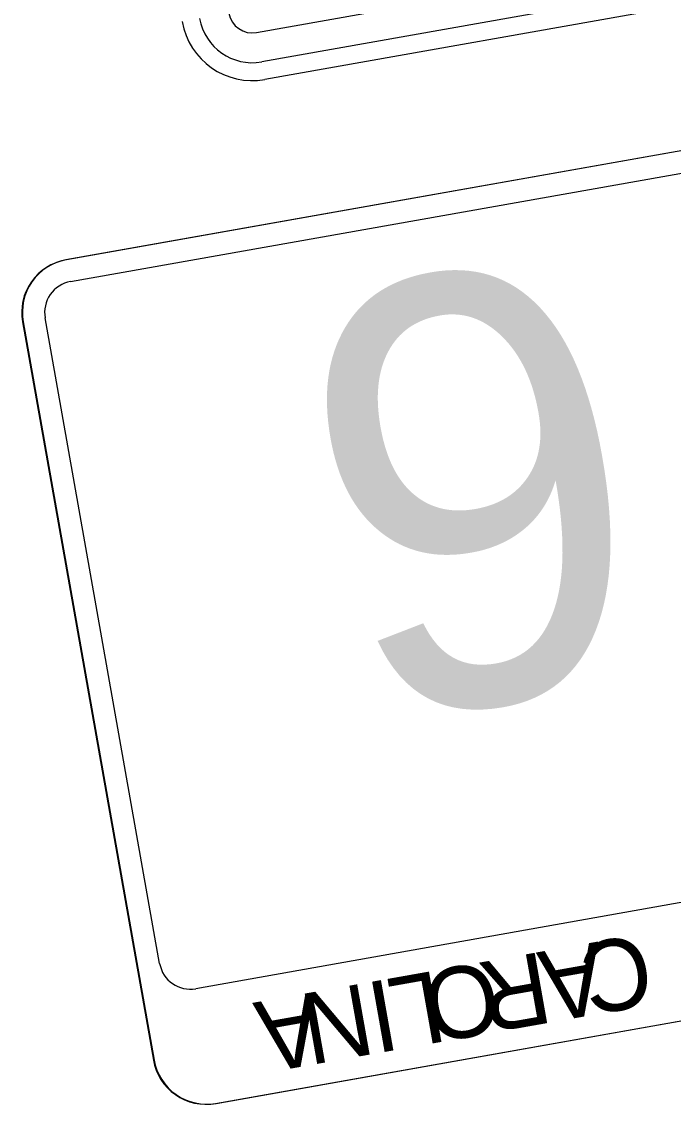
# Model space of a CAD drawing. Extents: x 1581789 to 1622364, y 1043167 to 1103486.
# Drawn here: x 1611854.63 to 1611863.76, y 1090933.43 to 1090948.59 of the extents above; entities that cross this region are included whole.
import ezdxf

# ---------------------------------------------------------------- set-up
doc = ezdxf.new("R2010")
doc.units = 0
doc.layers.add('RD_PD_ALT1_TX', color=7, linetype='Continuous')

msp = doc.modelspace()

# ---------------------------------------------------------------- linework, layer by layer
at = {"layer": 'RD_PD_ALT1_TX'}
for p, q in [((1611869.851, 1090949.875), (1611858.036, 1090947.779)), ((1611873.454, 1090948.483), (1611855.249, 1090945.254)), ((1611864.293, 1090946.858), (1611855.258, 1090945.255)), ((1611854.641, 1090944.384), (1611856.474, 1090934.046)), ((1611854.651, 1090944.386), (1611856.484, 1090934.047)), ((1611857.344, 1090933.438), (1611875.55, 1090936.667)), ((1611857.354, 1090933.44), (1611875.559, 1090936.669))]:
    msp.add_line(p, q, dxfattribs=at)
for points in [[(1611857.919, 1090948.435), (1611869.735, 1090950.531)], [(1611869.807, 1090950.121), (1611857.992, 1090948.025)], [(1611855.313, 1090944.948), (1611864.347, 1090946.55), (1611873.518, 1090948.177)], [(1611856.562, 1090935.399), (1611854.958, 1090944.44)], [(1611875.274, 1090938.279), (1611868.552, 1090937.083), (1611868.574, 1090937.039), (1611868.811, 1090937.027), (1611868.889, 1090936.915), (1611868.994, 1090936.893), (1611869.131, 1090936.815), (1611869.241, 1090936.557), (1611868.946, 1090936.026), (1611868.329, 1090935.673), (1611868.276, 1090935.579), (1611866.628, 1090935.348), (1611866.218, 1090935.718), (1611865.219, 1090935.559), (1611864.869, 1090935.816), (1611864.177, 1090936.307), (1611857.069, 1090935.046)]]:
    msp.add_lwpolyline(points, dxfattribs=at)
for centre, radius, start, end in [((1611857.861, 1090948.764), 0.333, 190.0581, 280.0578), ((1611857.861, 1090948.764), 1, 190.0581, 280.0578), ((1611857.861, 1090948.764), 0.75, 190.0581, 280.0578), ((1611855.38, 1090944.515), 0.75, 100.0581, 190.0583), ((1611855.389, 1090944.517), 0.75, 100.0581, 190.0583), ((1611855.389, 1090944.517), 0.438, 100.0581, 190.0583), ((1611856.992, 1090935.476), 0.437, 190.1563, 280.1562), ((1611857.213, 1090934.177), 0.75, 190.058, 280.0582), ((1611857.223, 1090934.178), 0.75, 190.058, 280.0582)]:
    msp.add_arc(centre, radius, start, end, dxfattribs=at)

# ---------------------------------------------------------------- texts
for s, height, p in [('6', 6, (1611862.66, 1090945.4)), ('A', 1, (1611862.705, 1090935.707)), ('C', 1, (1611863.355, 1090935.822)), ('R', 1, (1611861.923, 1090935.568)), ('O', 1, (1611861.218, 1090935.443)), ('L', 1, (1611860.442, 1090935.305)), ('N', 1, (1611859.437, 1090935.127)), ('I', 1, (1611859.783, 1090935.188)), ('A', 1, (1611858.733, 1090935.002))]:
    msp.add_text(s, height=height, rotation=190.058, dxfattribs=at).set_placement(p)

doc.saveas('drawing.dxf')
